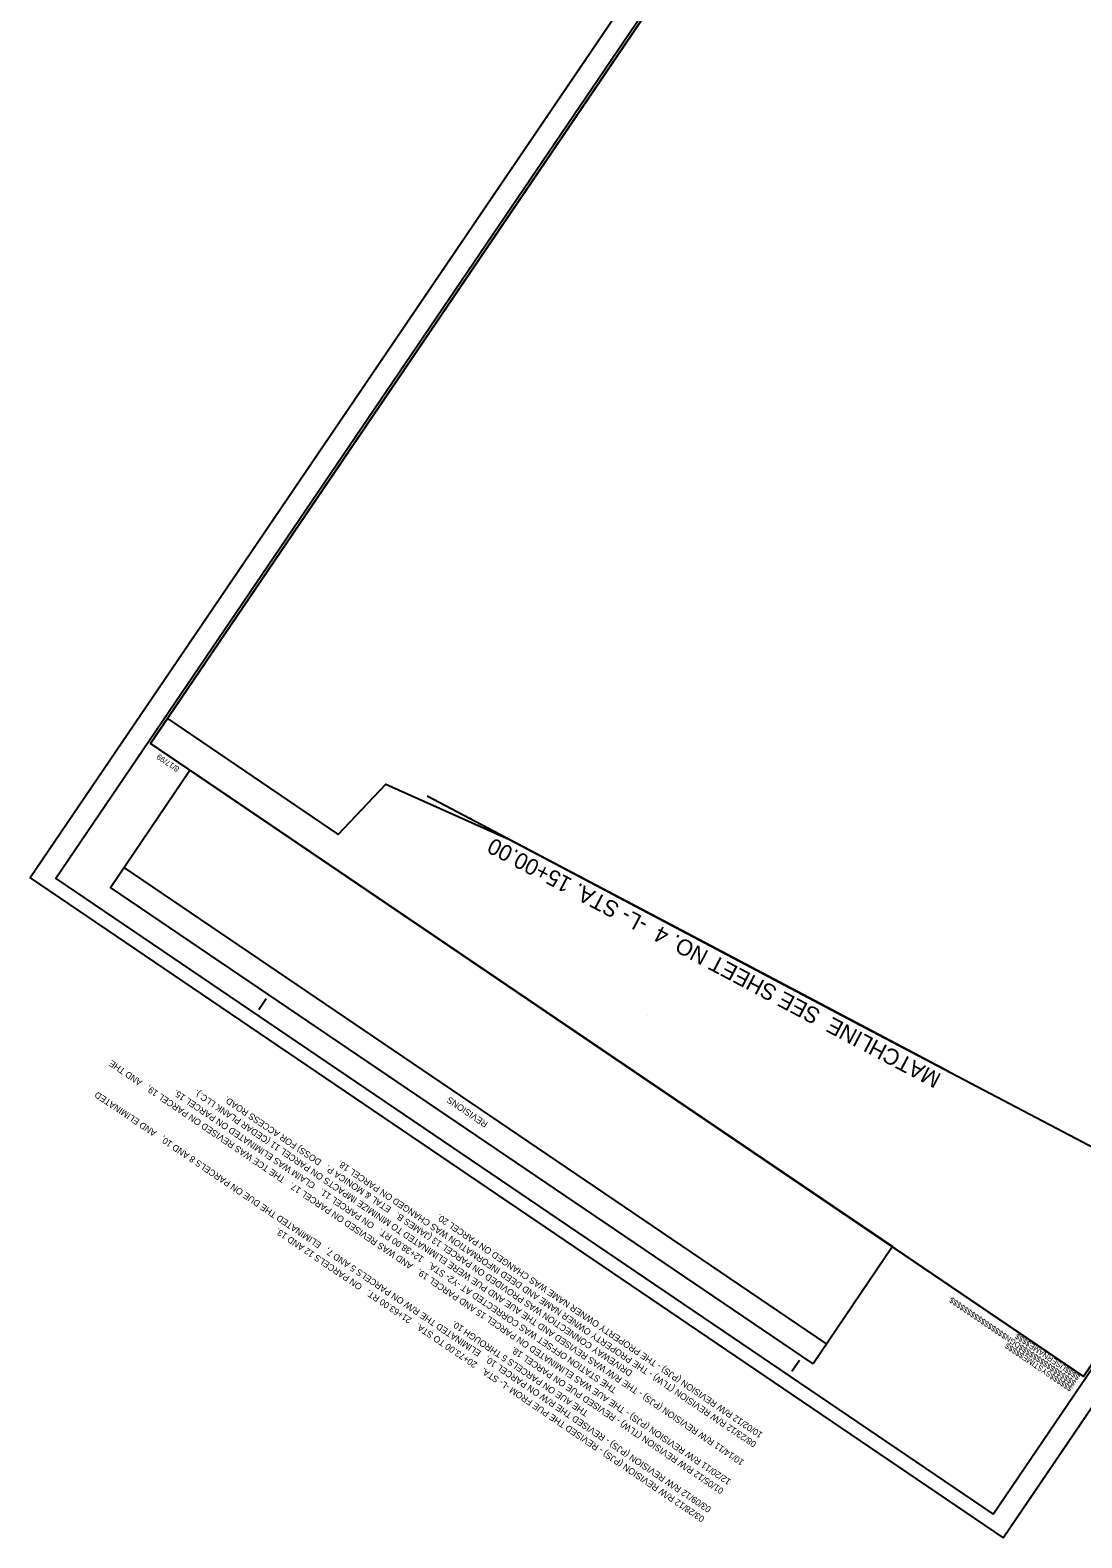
# Model space of a CAD drawing. Extents: x 1975407 to 1977258, y 778272 to 780396.
# Drawn here: x 1975407 to 1976387, y 778272 to 779677 of the extents above; entities that cross this region are included whole.
import ezdxf

# ---------------------------------------------------------------- set-up
doc = ezdxf.new("R2010")
doc.units = 0
for name, color, linetype in [('Matchline', 7, 'Continuous'), ('Matchline Text', 7, 'Continuous'), ('Sheet Block Revision CELL', 7, 'Continuous'), ('Sheet Clip Boundary CELL', 7, 'Continuous'), ('Sheet Cutting Line CELL', 7, 'Continuous'), ('Sheet Plan CELL', 7, 'Continuous'), ('Sheet Plan Layout CELL', 7, 'Continuous'), ('Sheet Plot Border Inside CELL', 7, 'Continuous'), ('Sheet Plot Border Outside CELL', 7, 'Continuous')]:
    doc.layers.add(name, color=color, linetype=linetype)

msp = doc.modelspace()

# ---------------------------------------------------------------- linework, layer by layer
at = {"layer": 'Matchline'}
msp.add_lwpolyline([(1976262.6, 778706.4), (1976019.4, 778834.9), (1975776.9, 778963.1)], dxfattribs=at)
at = {"layer": 'Sheet Block Revision CELL'}
msp.add_line((1976148.9, 778452.7), (1975494.6, 778896.6), dxfattribs=at)
msp.add_lwpolyline([(1976136.3, 778434.1), (1975481.9, 778877.8), (1975556, 778987.1), (1976210.4, 778543.5)], close=True, dxfattribs=at)
at = {"layer": 'Sheet Clip Boundary CELL'}
msp.add_lwpolyline([(1976497.2, 778583.1), (1977189.9, 779604.2), (1976973.8, 779681.3), (1976888, 779765.6), (1976619.5, 780027.3), (1976496, 780074.9), (1976389.8, 779918.3), (1976214.8, 780037.1), (1975535, 779035.2), (1975693.9, 778927.3), (1975738.3, 778974.2), (1975853.6, 778922.6), (1976185.1, 778747.3)], close=True, dxfattribs=at)
at = {"layer": 'Sheet Cutting Line CELL'}
for p, q in [((1976352.4, 780279.9), (1975407.2, 778886.8)), ((1976313.3, 778272), (1977258.5, 779665.2)), ((1975407.2, 778886.8), (1976313.3, 778272))]:
    msp.add_line(p, q, dxfattribs=at)
at = {"layer": 'Sheet Plan CELL'}
for p, q in [((1975519.3, 779012), (1975519.3, 779012)), ((1975620, 778764.1), (1975627, 778774.5)), ((1975981.8, 778758.6), (1975981.8, 778758.6)), ((1976116.5, 778427.3), (1976123.6, 778437.6))]:
    msp.add_line(p, q, dxfattribs=at)
for points in [[(1976361.4, 780253.3), (1975519.3, 779012), (1976388.1, 778422.4), (1977230.3, 779663.7)], [(1976388.1, 778422.4), (1975519.3, 779011.9), (1976249.1, 780087.7), (1976373.3, 780003.5), (1976485.6, 780169), (1977230.3, 779663.7)]]:
    msp.add_lwpolyline(points, close=True, dxfattribs=at)
at = {"layer": 'Sheet Plan Layout CELL'}
msp.add_lwpolyline([(1975519.3, 779011.9), (1976388.1, 778422.4), (1977230.3, 779663.7), (1976536.4, 780134.5), (1976402.1, 779936.5), (1976227.1, 780055.3)], close=True, dxfattribs=at)
at = {"layer": 'Sheet Plot Border Inside CELL'}
msp.add_lwpolyline([(1976304, 778294), (1977239.4, 779672.7), (1976366.4, 780265), (1975431, 778886.3)], close=True, dxfattribs=at)
at = {"layer": 'Sheet Plot Border Outside CELL'}
msp.add_lwpolyline([(1976313.3, 778272), (1977258.5, 779665.2), (1976352.4, 780279.9), (1975407.2, 778886.8)], close=True, dxfattribs=at)

# ---------------------------------------------------------------- texts
at = {"layer": 'Matchline Text'}
msp.add_text('MATCHLINE  SEE SHEET NO. 4  -L- STA. 15+00.00', height=15, rotation=152.1381, dxfattribs=at).set_placement((1976256.8, 778703.6))
at = {"layer": 'Sheet Block Revision CELL'}
for s, p in [('12/20/11 R/W REVISION (PJS) - THE AUE WAS ELIMINATED ON PARCEL 15 AND PARCEL 19,   AND WAS REVISED ON PARCEL 17.   THE TCE WAS REVISED ON PARCEL 19,   AND THE', (1976060.5, 778325.7)), ('03/09/12 R/W REVISION (PJS) - REVISED THE R/W ON PARCEL 10,   ELIMINATED THE R/W ON PARCELS 5 AND 7,   ELIMINATED THE DUE ON PARCELS 8 AND 10,   AND ELIMINATED', (1976042, 778300)), ('THE STATION OFFSET WAS CORRECTED AT -Y2- STA.   12+38.00 RT.   ON PARCEL 11.   CLAIM WAS ELIMINATED ON PARCEL 15.', (1975954, 778411.3)), ('10/14/11 R/W REVISION (PJS) - THE R/W WAS REVISED AND THE AUE AND PUE WERE ELIMINATED TO MINIMIZE IMPACTS ON PARCEL 11 (CEDAR PLANK LLC.).', (1976072.7, 778343.8)), ('DRIVEWAY CONNECTION WAS PROVIDED ON PARCEL 13 (JAMES B.   ETAL & MONICA P.   DOSS) FOR ACCESS ROAD.', (1975968.7, 778427)), ('REVISIONS', (1975834.1, 778658.8)), ('08/23/12 R/W REVISION (TLW) - THE PROPERTY OWNER NAME AND DEED INFORMATION WAS CHANGED ON PARCEL 18.', (1976084.1, 778360.8)), ('10/02/12 R/W REVISION (PJS) - THE PROPERTY OWNER NAME WAS CHANGED ON PARCEL 20.', (1976090, 778369.4)), ('03/28/12 R/W REVISION (PJS) - REVISED THE PUE FROM -L- STA.   20+73.00 TO STA.   21+63.00 RT.   ON PARCELS 12 AND 13.', (1976035.9, 778291.1)), ('THE AUE ON PARCELS 5 THROUGH 10.', (1975927.7, 778389.6)), ('01/05/12 R/W REVISION (TLW) - REVISED PUE ON PARCEL 18.', (1976053.7, 778317.3))]:
    msp.add_text(s, height=6, rotation=145.8441, dxfattribs=at).set_placement(p)
at = {"layer": 'Sheet Plan CELL'}
for s, p in [('8/17/99', (1975546.6, 778989.5)), ('$$$$$$$$$$$$$$$$DGN$$$$$$$$$$$$$$$$', (1976381.9, 778417.5)), ('$$$$USERNAME$$$$', (1976385.6, 778422.9)), ('$$$$$$SYSTIME$$$$$', (1976378.5, 778412.4))]:
    msp.add_text(s, height=5.25, rotation=145.8441, dxfattribs=at).set_placement(p)

doc.saveas('drawing.dxf')
